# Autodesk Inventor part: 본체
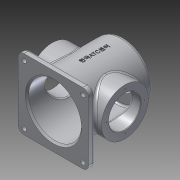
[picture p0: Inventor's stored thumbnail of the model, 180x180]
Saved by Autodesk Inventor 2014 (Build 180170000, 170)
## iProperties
Created: 2015-10
Part Number: 본체
Material: 알루미늄 6061
Document SubType Name: Modeling
Designer: Owner
Density: 2.71 g/cm^3
Appearance: 알루미늄 - 평지
Mass: 1074.97 g
Surface Area: 1087.87 cm^2
Volume: 396.669 cm^3
Author: Owner
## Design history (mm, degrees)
sketch "스케치1"
  geometry: L1 (0, 80.726)-(0, -90.76); L2 (-27, 65)-(-40, 65); L3 (-40, 65)-(-40, 60); L4 (-40, 60)-(-50, 60); L5 (-50, 60)-(-50, -60); L6 (-50, -60)-(-45, -60); L7 (-45, -60)-(-45, 52); L8 (-45, 52)-(-27, 52); L9 (-27, 52)-(-27, 65); 1 further point
  constraints: 18 end point, 6 parallel, 2 perpendicular, 1 point on line, 1 vertical
  dimensions: "d0" = 90 diameter of L7 L1; "d1" = 54 diameter of L9 L1; "d2" = 80 diameter of L3 L1; "d3" = 100 diameter of L5 L1; "d4" = 120 distance between parallel lines of L6 L4; "d5" = 13 distance between parallel lines of L2 L8; "d6" = 5 distance between parallel lines of L2 L4; "d7" = 60 distance from line of L6 point (0, 0)
revolve "회전1" sketch "스케치1" stored, may be unused: angle "d8" = 90 deg
node "작업 평면1"
sketch "스케치2"
  geometry: L1 (50, -60)-(-50, -60); L2 (-60, -50)-(-60, 50); L3 (-50, 60)-(50, 60); L4 (60, 50)-(60, -50); L5 (60, -60)-(-60, 60); L6 (-60, -60)-(60, 60); C1 r 45 at (0, 0) reference; A1 r 10 centre (-50, 50) between (-50, 60) and (-60, 50); A2 r 10 centre (50, 50) between (60, 50) and (50, 60); A3 r 10 centre (50, -50) between (50, -60) and (60, -50); A4 r 10 centre (-50, -50) between (-60, -50) and (-50, -60); 1 further point
  constraints: 12 end point, 8 point on circle, 8 point on line, 8 tangent, 4 centre point, 3 equal radius, 2 midpoint, 2 parallel, 1 horizontal, 1 perpendicular
  dimensions: "d10" = 120 distance of L5.end L6.end; "d11" = 120 distance of L6.start L5.end; "d12" = 10 radius of A1
extrude "돌출1" join sketch "스케치2" distance "d13" = 10; taper "d14" = 0 deg
node "작업 평면3"
  node "작업 평면2"
sketch "스케치4"
  geometry: C1 r 40 at (0, 0); 1 further point
  constraints: 1 centre point, 1 coincident
  dimensions: "d17" = 80 diameter of C1
extrude "돌출2" join sketch "스케치4" stored distance "d18" = 10; taper "d19" = 0 deg
hole "구멍1" diameter "d22" = 54; stored, may be unused: countersink angle "d26" = 90 deg, drill point angle "d28" = 0 deg; dims "d20" = 10, "d21" = 10, "d23" = 6, "d24" = 4, "d25" = 2, "d27" = 8
sketch "스케치5" dims "d29" = 65
  geometry: L1 (0, 0)-(40.527, 40.527); L2 (0, 0)-(57.313, 0); C1 r 27 at (0, 0) reference; 2 further points
  constraints: 4 end point, 2 coincident, 1 equal length, 1 horizontal, 1 point on line, 3 other
  dimensions: "d30" = 45 deg angle of L2 L1
hole "구멍2" sketch "스케치5" at (22.981, 22.981) diameter "d31" = 3.242; stored, may be unused: countersink angle "d35" = 90 deg, drill point angle "d37" = 118 deg; dims "d32" = 8, "d33" = 4, "d34" = 2, "d36" = 10
sketch "스케치6"
  geometry: C1 r 27 at (0, 0) reference; 1 further point
  constraints: 1 vertical alignment
  dimensions: "d42" = 32.5 distance of C1.centre point (0, 32.5)
hole "구멍3" sketch "스케치6" at (0, 32.5) diameter "d43" = 3.242; stored, may be unused: countersink angle "d47" = 90 deg, drill point angle "d49" = 118 deg; dims "d44" = 8, "d45" = 4, "d46" = 2, "d48" = 10
sketch "스케치7"
  geometry: A1 r 10 centre (-50, -50) between (-60, -50) and (-50, -60) reference; A2 r 10 centre (50, -50) between (50, -60) and (60, -50) reference; A3 r 10 centre (50, 50) between (60, 50) and (50, 60) reference; A4 r 10 centre (-50, 50) between (-50, 60) and (-60, 50) reference; 4 further points
  constraints: 4 coincident
hole "구멍4" sketch "스케치7" at (-50, 50), (-50, -50), (50, -50), (50, 50) diameter "d53" = 8; stored, may be unused: countersink angle "d57" = 90 deg, drill point angle "d59" = 0 deg; dims "d54" = 8, "d55" = 4, "d56" = 2, "d58" = 10
fillet "모깎기1" dims "d60" = 5, "d61" = 3
chamfer "모따기1" distance "d62" = 3; stored, may be unused: second distance "d63" = 2, angle "d64" = 45 deg
chamfer "모따기2" distance "d65" = 1; stored, may be unused: second distance "d66" = 2, angle "d67" = 45 deg
node "작업 평면7"
sketch "스케치8"
  geometry: L1 (50, -60)-(-50, -60) reference; 2 further points
  constraints: 1 vertical alignment, 1 other
  dimensions: "d68" = 70 distance from line of L1 point (0, 10)
feature "엠보싱1" sketch "스케치8" dims "d0" = 90, "d1" = 54, "d2" = 80, "d3" = 100, "d4" = 120, "d5" = 13, "d6" = 5, "d7" = 60, "d69" = 0.5, "d70" = 0
node "솔리드1"
pattern_circular "원형 패턴2" dims angle "d51" = 360 deg
pattern_circular "원형 패턴1" dims angle "d39" = 360 deg
mirror "대칭1"
other parameters: "d15" = 12
